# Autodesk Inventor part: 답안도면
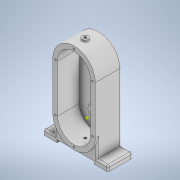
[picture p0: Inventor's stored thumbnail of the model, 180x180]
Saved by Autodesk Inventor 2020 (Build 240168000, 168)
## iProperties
Created: 2021-05
Part Number: 답안도면
Material: 일반
Document SubType Name: Modeling
Designer: OWner
Density: 1 g/cm^3
Appearance: 기본값
Author: OWner
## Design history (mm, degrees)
sketch "스케치1"
  geometry: 1 further point
sketch "스케치2"
  geometry: L1 (0, 90)-(0, 0); L2 (-40, 90)-(-40, 0); L3 (40, 0)-(40, 90); A1 r 40 centre (0, 90) between (40, 90) and (-40, 90); A2 r 40 centre (0, 0) between (-40, 0) and (40, 0); 1 further point
  constraints: 8 end point, 4 point on circle, 4 tangent, 2 centre point, 1 midpoint, 1 parallel, 1 vertical
  dimensions: "d1" = 80 distance between parallel lines of L2 L3; "d2" = 45 distance of point (0, 45) L1.end
extrude "돌출1" new body sketch "스케치2" stored distance "d3" = 49; taper "d4" = 0 deg
sketch "스케치3"
  geometry: L1 (0, 0)-(0, 90); L2 (-31, 0)-(-31, 90); L3 (31, 90)-(31, 0); A1 r 31 centre (0, 0) between (-31, 0) and (31, 0); A2 r 31 centre (0, 90) between (31, 90) and (-31, 90); 1 further point
  constraints: 8 end point, 4 point on circle, 4 tangent, 2 centre point, 1 midpoint, 1 parallel, 1 vertical
  dimensions: "d5" = 45 distance of point (0, 45) L1.start; "d6" = 31 radius of A2
extrude "돌출2" cut sketch "스케치3" distance "d7" = 41; taper "d8" = 0 deg
sketch "스케치9"
  geometry: L1 (0, 0)-(0, 90); L2 (-26, 0)-(-26, 90); L3 (26, 90)-(26, 0); A1 r 26 centre (0, 0) between (-26, 0) and (26, 0); A2 r 26 centre (0, 90) between (26, 90) and (-26, 90); 1 further point
  constraints: 8 end point, 4 point on circle, 4 tangent, 2 centre point, 1 midpoint, 1 parallel, 1 vertical
  dimensions: "d34" = 45 distance of L1.start point (0, 45); "d35" = 52 distance between parallel lines of L3 L2
extrude "돌출10" join sketch "스케치9" distance "d36" = 8; taper "d37" = 0 deg
sketch "스케치10"
  geometry: C1 r 14 at (0, 90); A1 r 26 centre (0, 90) between (26, 90) and (-26, 90) reference; 1 further point
  constraints: 1 centre point, 1 coincident
  dimensions: "d38" = 28 diameter of C1
extrude "돌출11" cut sketch "스케치10" distance "d39" = 4; taper "d40" = 0 deg
sketch "스케치11"
  geometry: C1 r 14 at (0, 0) reference; C2 r 11 at (0, 0); 1 further point
  constraints: 1 centre point, 1 coincident
  dimensions: "d41" = 22 diameter of C2
extrude "돌출12" cut sketch "스케치11" distance "d42" = 4; taper "d43" = 0 deg
sketch "스케치12"
  geometry: C1 r 14 at (0, 90); C2 r 14 at (0, 0); A1 r 31 centre (0, 90) between (31, 90) and (-31, 90) reference; 1 further point
  constraints: 2 centre point, 2 coincident
  dimensions: "d44" = 28 diameter of C1; "d45" = 28 diameter of C2
extrude "돌출13" cut sketch "스케치12" distance "d46" = 8; taper "d47" = 0 deg
sketch "스케치13"
  geometry: C1 r 10 at (0, 0); 1 further point
  constraints: 1 centre point, 1 coincident
  dimensions: "d48" = 20 diameter of C1
extrude "돌출14" cut sketch "스케치13" distance "d49" = 4; taper "d50" = 0 deg
node "작업 평면1"
sketch "스케치14"
  geometry: 1 further point
sketch "스케치15"
  geometry: L1 (40, 24.5)-(-40, 24.5) reference; L2 (0, 24.5)-(0, 3.5); C1 r 6 at (0, 3.5); 2 further points
  constraints: 2 coincident, 2 end point, 1 centre point, 1 midpoint, 1 vertical
  dimensions: "d52" = 21 distance of L2.start L2.end; "d53" = 12 diameter of C1
extrude "돌출15" join sketch "스케치15" distance "d54" = 3; taper "d55" = 0 deg
sketch "스케치16"
  geometry: C1 r 6 at (0, 0); A1 r 6 centre (0, 0) between (0, 6) and (0, -6) reference; 3 further points
  constraints: 1 centre point, 1 coincident
  dimensions: "d56" = 12 diameter of C1
extrude "돌출16" join sketch "스케치16" distance "d57" = 5; taper "d58" = 0 deg
sketch "스케치17"
  geometry: C1 r 6 at (0, 0) reference; 2 further points
  constraints: 1 coincident
hole "구멍1" sketch "스케치17" at (0, 0) diameter "d59" = 4.917; stored, may be unused: countersink angle "d63" = 90 deg, drill point angle "d65" = 118 deg; dims "d60" = 12, "d61" = 4, "d62" = 2, "d64" = 29.6
sketch "스케치18"
  geometry: L1 (0, 0)-(0, 90); L2 (35, 0)-(35, 90); L3 (-35, 90)-(-35, 0); A1 r 35 centre (0, 0) between (-35, 0) and (35, 0); A2 r 35 centre (0, 90) between (35, 90) and (-35, 90); 7 further points
  constraints: 8 end point, 6 point on circle, 4 coincident, 4 tangent, 2 centre point, 1 midpoint, 1 parallel, 1 vertical
  dimensions: "d66" = 45 distance of point (0, 45) L1.start; "d67" = 35 radius of A2
hole "구멍2" sketch "스케치18" at (-35, 90), (35, 90), (0, 125), (35, 0), (0, -35), (-35, 0) diameter "d68" = 3.242; stored, may be unused: countersink angle "d72" = 90 deg, drill point angle "d74" = 118 deg; dims "d69" = 8, "d70" = 4, "d71" = 2, "d73" = 10
sketch "스케치19"
  geometry: 1 further point
node "작업 평면2"
sketch "스케치20"
  geometry: L1 (61, -24.5)-(35, -24.5); L2 (35, -24.5)-(35, 21.5); L3 (35, 21.5)-(61, 21.5); L4 (61, 21.5)-(61, -24.5); L5 (40, 24.5)-(-40, 24.5) reference; L6 (-26, -32.5)-(26, -32.5) reference; L7 (0, -32.5)-(0, 39.099); L8 (-61, -24.5)-(-35, -24.5); L9 (-35, -24.5)-(-35, 21.5); L10 (-35, 21.5)-(-61, 21.5); L11 (-61, 21.5)-(-61, -24.5); 1 further point
  constraints: 18 end point, 4 parallel, 2 horizontal, 2 perpendicular, 1 midpoint, 1 vertical, 1 other
  dimensions: "d76" = 46 distance of L3.end L1.start; "d77" = 3 distance from line of L3.end L5; "d78" = 61 distance from line of L1.start L7; "d79" = 61 distance from line of L8.start L7; "d80" = 46 distance of L10.end L8.start; "d81" = 3 distance between parallel lines of L10 L5; "d82" = 70 distance between parallel lines of L9 L2
extrude "돌출17" join sketch "스케치20" distance "d83" = 10; taper "d84" = 0 deg
sketch "스케치21"
  geometry: L1 (0, 0)-(26, 0) reference; L2 (26, 0)-(26, 5); L3 (26, 0)-(26, 10) reference; L4 (26, 5)-(96, 5); L5 (96, 0)-(96, 10) reference; L6 (21, 47)-(21, 10); L7 (0, 10)-(26, 10) reference; L8 (101, 47)-(101, 10); L9 (96, 10)-(122, 10) reference; L10 (21, 10)-(26, 10); L11 (26, 10)-(26, 5); L12 (96, 5)-(96, 10); L13 (101, 10)-(96, 10); A1 r 40 centre (61, 47) between (21, 47) and (101, 47) reference; A2 r 40 centre (61, 47) between (21, 47) and (101, 47); 1 further point
  constraints: 16 end point, 3 collinear, 2 midpoint, 2 point on circle, 2 point on line, 2 vertical, 1 centre point, 1 concentric, 1 perpendicular
  dimensions: "d85" = 5 distance of L1.end L2.end (derived)
extrude "돌출18" join sketch "스케치21" distance "d86" = 46; taper "d87" = 0 deg
sketch "스케치22"
  geometry: L1 (0, 0)-(0, 44.011); L2 (-26, 0)-(-26, 60); L3 (26, 60)-(26, 0); L4 (-26, 60)-(26, 60); L5 (26, 0)-(26, 90) reference; C1 r 11 at (0, 90) reference; A1 r 26 centre (0, 0) between (-26, 0) and (26, 0); 1 further point
  constraints: 10 end point, 2 point on circle, 2 tangent, 1 centre point, 1 coincident, 1 parallel, 1 perpendicular, 1 point on line, 1 vertical
  dimensions: "d88" = 30 vertical distance of L2.end point (0, 90)
extrude "돌출19" join sketch "스케치22" distance "d89" = 3; taper "d90" = 0 deg
sketch "스케치23"
  geometry: L1 (-25.882, -35)-(24.286, -35); L2 (-85.4, -47)-(85.4, -47) reference; L3 (0, 0)-(0, -58.606); C1 r 10 at (0, 0) reference; 1 further point
  constraints: 4 end point, 2 horizontal, 1 vertical
  dimensions: "d91" = 12 distance between parallel lines of L2 L1
sketch "스케치24"
  geometry: C1 r 2.458 at (35, 28) reference; 2 further points
  constraints: 1 coincident
hole "구멍3" sketch "스케치24" at (35, 28) diameter "d92" = 4.917; stored, may be unused: countersink angle "d96" = 90 deg, drill point angle "d98" = 118 deg; dims "d93" = 12, "d94" = 12, "d95" = 1, "d97" = 17.1
fillet "모깎기1" dims "d99" = 3
fillet "모깎기2" dims "d100" = 3
fillet "모깎기3" dims "d101" = 3
fillet "모깎기4" dims "d102" = 3
extrude "돌출20" join sketch "스케치23" distance "d103" = 1; taper "d104" = 0 deg
chamfer "모따기1" distance "d105" = 1; stored, may be unused: second distance "d106" = 2, angle "d107" = 45 deg
chamfer "모따기2" distance "d108" = 1; stored, may be unused: second distance "d109" = 2, angle "d110" = 45 deg
node "솔리드1"
feature "A9D066F2-1C7D-4E18-AEED-F7BC21143FA4" dims "d68" = 3.242, "d69" = 8, "d70" = 4, "d71" = 2, "d72" = 90 deg, "d73" = 10, "d74" = 118 deg
other parameters: "d75" = -47
